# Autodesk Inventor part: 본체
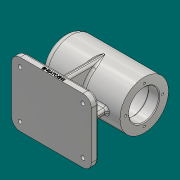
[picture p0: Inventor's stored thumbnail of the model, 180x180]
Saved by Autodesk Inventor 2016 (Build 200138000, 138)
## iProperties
Created: 2020-10
Part Number: 본체
Material: 알루미늄 6061
Document SubType Name: Modeling
Designer: 605-15
Density: 2.7 g/cm^3
Appearance: 알루미늄 - 평지
Mass: 1026.27 g
Surface Area: 757.929 cm^2
Volume: 380.101 cm^3
Author: 605-15
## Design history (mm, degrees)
sketch "스케치1"
  geometry: L1 (-56, 10)-(56, 10); L2 (56, 10)-(56, 0); L3 (56, 0)-(-56, 0); L4 (-56, 0)-(-56, 10); 2 further points
  constraints: 8 end point, 2 parallel, 1 coincident, 1 horizontal, 1 midpoint, 1 perpendicular
  dimensions: "d0" = 112 distance of L1.start L1.end; "d1" = 10 distance of L1.end L2.end
extrude "돌출1" new body sketch "스케치1" stored distance "d2" = 90; taper "d3" = 0 deg
sketch "스케치2"
  geometry: L1 (-56, 108)-(56, 108); L2 (56, 108)-(56, 74); L3 (56, 74)-(-56, 74); L4 (-56, 74)-(-56, 108); L5 (56, 95)-(41, 95); L6 (41, 95)-(41, 98); L7 (41, 98)-(-13, 98); L8 (-13, 98)-(-13, 95); L9 (-13, 95)-(-25, 95); L10 (-25, 95)-(-25, 91.5); L11 (-25, 91.5)-(-43, 91.5); L12 (-43, 91.5)-(-43, 90); L13 (-43, 90)-(-47, 90); L14 (-47, 90)-(-47, 84.5); L15 (-47, 84.5)-(-50, 84.5); L16 (-50, 84.5)-(-50, 74); L17 (56, 0)-(-56, 0) reference; 3 further points
  constraints: 32 end point, 11 perpendicular, 4 point on line, 2 horizontal, 2 midpoint, 2 parallel, 1 vertical alignment
  dimensions: "d5" = 112 distance of L1.start L1.end; "d6" = 74 distance between parallel lines of L17 L3; "d7" = 15 distance of L5.start L5.end; "d9" = 3 distance of L14.end L15.end; "d10" = 4 distance of L12.end L13.end; "d11" = 18 distance of L10.end L11.end; "d12" = 12 distance of L8.end L9.end; "d13" = 54 distance of L6.end L7.end; "d14" = 21 diameter of L15 L3; "d15" = 32 diameter of L13 L3; "d16" = 35 diameter of L11 L3; "d17" = 48 diameter of L7 L3; "d18" = 42 diameter of L9 L3; "d19" = 68 diameter of L1 L3
revolve "회전1" sketch "스케치2" stored, may be unused: angle "d20" = 90 deg
fillet "모깎기1" dims "d21" = 12, "d22" = 10
fillet "모깎기2" dims "d23" = 0.3, "d24" = 3
sketch "스케치3"
  geometry: A1 r 9 centre (88, -9) between (97, -9) and (88, 0) reference; A2 r 9 centre (0, -9) between (0, 0) and (-9, -9) reference; A3 r 9 centre (0, -75) between (-9, -75) and (0, -84) reference; A4 r 9 centre (88, -75) between (88, -84) and (97, -75) reference; 1 further point
hole "구멍1" sketch "스케치3" at (0, -9), (0, -75), (88, -75), (88, -9) diameter "d25" = 5.5; stored, may be unused: countersink angle "d29" = 90 deg, drill point angle "d31" = 118 deg; dims "d26" = 6, "d27" = 9.5, "d28" = 5.4, "d30" = 8
sketch "스케치4" dims "d32" = 52
  geometry: C1 r 34 at (0, 0) reference; C2 r 21 at (0, 0) reference; 3 further points
  constraints: 2 vertical alignment, 1 coincident, 2 other
hole "구멍2" sketch "스케치4" at (0, 26) diameter "d33" = 3.242; stored, may be unused: countersink angle "d37" = 90 deg, drill point angle "d39" = 118 deg; dims "d34" = 8, "d35" = 9.5, "d36" = 5.4, "d38" = 11
sketch "스케치5"
  geometry: L1 (100, -75)-(100, -9) reference; L2 (100, -42)-(-12, -42); L3 (-12, -75)-(-12, -9) reference; L4 (6, -38)-(82, -38); L5 (82, -38)-(82, -46); L6 (82, -46)-(6, -46); L7 (6, -46)-(6, -38); L8 (6, -38)-(82, -46); L9 (82, -38)-(6, -46); 3 further points
  constraints: 14 end point, 6 midpoint, 2 parallel, 1 horizontal, 1 perpendicular
  dimensions: "d44" = 8 distance of L6.end L4.start; "d45" = 18 distance between parallel lines of L5 L1
extrude "돌출2" join sketch "스케치5" stored distance "d46" = 10; taper "d47" = 0 deg
sketch "스케치6"
  geometry: L1 (10, 33)-(10, -33) reference; L2 (10, 42)-(10, 33) reference; L3 (10, 34)-(74, 34); L4 (7, -33)-(7, 33) reference; L5 (0, 0)-(108, 0); A1 r 34 centre (74, 0) between (74, 34) and (108, 0) reference
  constraints: 4 end point, 2 point on circle, 1 horizontal, 1 perpendicular, 1 point on line
  dimensions: "d48" = 34 distance between parallel lines of L5 L3
feature "리브1" sketch "스케치6" dims "d49" = 1, "d50" = 8, "d51" = 0, "d52" = 0, "d53" = 1, "d54" = 1
chamfer "모따기1" distance "d55" = 1; stored, may be unused: second distance "d56" = 2, angle "d57" = 45 deg
fillet "모깎기3" dims "d58" = 3
fillet "모깎기4" dims "d59" = 3
sketch "스케치7"
  geometry: L1 (-44, 0)-(44, 0) reference; L2 (-15.792, 3.294)-(15.792, 3.294); L3 (15.792, 3.294)-(15.792, 2.706); L4 (15.792, 2.706)-(-15.792, 2.706); L5 (-15.792, 2.706)-(-15.792, 3.294); L6 (-15.792, 3)-(0, 3); L7 (0, 2.706)-(0, 3.294); L8 (56, 0)-(56, 7) reference; 1 further point
  constraints: 4 end point, 4 midpoint, 2 other
  dimensions: "d60" = 56 distance from line of L8 L7.start; "d61" = 3 distance from line of L1 L6.end
feature "엠보싱1" sketch "스케치7" dims "d0" = 112, "d1" = 10, "d5" = 112, "d6" = 74, "d7" = 15, "d9" = 3, "d10" = 4, "d11" = 18, "d12" = 12, "d13" = 54, "d14" = 21, "d15" = 32, "d16" = 35, "d17" = 48, "d18" = 42, "d19" = 68, "d62" = 0.5, "d63" = 0
node "솔리드1"
pattern_circular "원형 패턴1" dims angle "d41" = 360 deg
mirror "대칭1"
